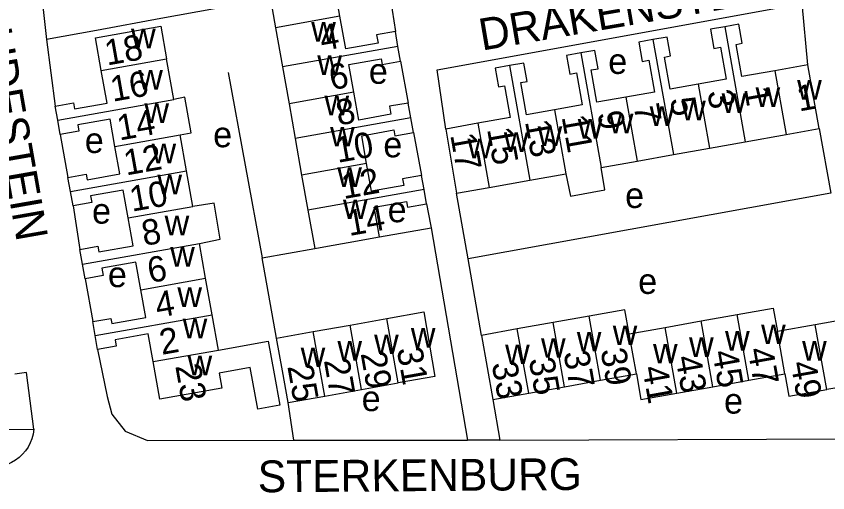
# Model space of a CAD drawing. Extents: x 157794 to 159375, y 380877 to 382306.
# Drawn here: x 158315.9 to 158443.4, y 381261.1 to 381335.9 of the extents above; entities that cross this region are included whole.
import ezdxf

# ---------------------------------------------------------------- set-up
doc = ezdxf.new("R2010")
doc.units = 0
for name, color, linetype in [('BLT_Basislijn', 7, 'Continuous'), ('BLT_Bebouwing', 7, 'Continuous'), ('BLT_Centroide', 7, 'Continuous'), ('BLT_Huisnummer', 7, 'Continuous'), ('BLT_Huisnummer_ tussenligend', 7, 'Continuous'), ('BLT_Onderverdeling_panden', 7, 'Continuous'), ('BLT_Straatnaam', 7, 'Continuous')]:
    doc.layers.add(name, color=color, linetype=linetype)

msp = doc.modelspace()

# ---------------------------------------------------------------- linework, layer by layer
at = {"layer": 'BLT_Basislijn'}
for p, q in [((158319.92, 381339.08), (158320.65, 381332.28)), ((158440.25, 381328.29), (158439.33, 381337.9)), ((158320.65, 381332.28), (158322.04, 381321.82)), ((158376.29, 381328.84), (158377.49, 381322.29)), ((158349.2, 381327.1), (158354.53, 381297.99)), ((158322.84, 381317.36), (158324.05, 381310.61)), ((158378.31, 381317.66), (158379.57, 381310.93)), ((158442.03, 381318.28), (158443.84, 381308.11)), ((158386.88, 381297.83), (158385.08, 381308.12)), ((158443.84, 381308.11), (158386.88, 381297.83)), ((158324.84, 381306.15), (158325.91, 381299.28)), ((158372.98, 381301.26), (158381.06, 381302.68)), ((158381.06, 381302.68), (158386.79, 381269.35)), ((158354.53, 381297.99), (158362.79, 381299.45)), ((158356.81, 381285.35), (158354.53, 381297.99)), ((158388.98, 381285.79), (158386.88, 381297.83)), ((158326.73, 381294.68), (158327.93, 381287.95)), ((158359.49, 381269.34), (158358.61, 381275.23)), ((158390.77, 381275.71), (158391.85, 381269.33)), ((158233.85, 381270.59), (158318.67, 381271.06)), ((158359.49, 381269.34), (158386.79, 381269.35)), ((158391.85, 381269.33), (158386.79, 381269.35))]:
    msp.add_line(p, q, dxfattribs=at)
for points in [[(158361.06, 381341.48), (158366.16, 381342.37), (158373.93, 381343.62), (158375.46, 381333.52)], [(158361.06, 381341.48), (158356.14, 381340.58), (158347.11, 381339.01), (158347.08, 381337.08), (158338.64, 381335.56), (158328.52, 381333.7), (158320.65, 381332.28)], [(158383.36, 381318.2), (158382.01, 381327.5), (158439.33, 381337.9)], [(158380.36, 381306.45), (158380.97, 381303.2), (158381.06, 381302.68)], [(158328.71, 381283.57), (158330.22, 381276.19), (158330.96, 381273.39), (158333.03, 381270.75), (158336.56, 381269.27), (158359.49, 381269.34)], [(158318.67, 381271.06), (158317.52, 381279.98), (158315.72, 381279.71)], [(158391.85, 381269.33), (158447.71, 381269.54), (158449.17, 381270.08), (158449.9, 381270.72), (158450.54, 381272.47), (158449.15, 381278.34)], [(158318.67, 381271.06), (158318.56, 381270.25), (158318.38, 381269.56), (158318.12, 381268.89), (158317.78, 381268.25), (158317.38, 381267.66), (158316.91, 381267.11), (158316.39, 381266.62), (158315.82, 381266.19), (158315.2, 381265.82), (158314.54, 381265.53), (158313.85, 381265.31), (158313.15, 381265.17), (158312.87, 381265.14)]]:
    msp.add_lwpolyline(points, dxfattribs=at)
at = {"layer": 'BLT_Bebouwing'}
for p, q in [((158356.64, 381334.12), (158357.73, 381327.96)), ((158375.87, 381331.18), (158375.46, 381333.52)), ((158376.29, 381328.84), (158375.87, 381331.18)), ((158340.68, 381322.83), (158339.54, 381329.22)), ((158357.73, 381327.96), (158358.76, 381322.17)), ((158440.25, 381328.29), (158435.06, 381327.36)), ((158442.03, 381318.28), (158440.25, 381328.29)), ((158358.76, 381322.17), (158359.72, 381316.74)), ((158377.9, 381319.97), (158377.49, 381322.29)), ((158322.44, 381319.59), (158322.04, 381321.82)), ((158322.84, 381317.36), (158322.44, 381319.59)), ((158378.31, 381317.66), (158377.9, 381319.97)), ((158388.42, 381319.1), (158383.36, 381318.2)), ((158342.67, 381311.62), (158341.66, 381317.28)), ((158383.36, 381318.2), (158385.08, 381308.12)), ((158430.4, 381316.2), (158436.84, 381317.35)), ((158436.84, 381317.35), (158442.03, 381318.28)), ((158359.72, 381316.74), (158360.74, 381310.98)), ((158424.8, 381315.2), (158430.4, 381316.2)), ((158419.12, 381314.19), (158424.8, 381315.2)), ((158413.42, 381313.17), (158419.12, 381314.19)), ((158407.77, 381312.16), (158413.42, 381313.17)), ((158343.66, 381306.05), (158342.67, 381311.62)), ((158360.74, 381310.98), (158361.73, 381305.45)), ((158379.96, 381308.69), (158379.57, 381310.93)), ((158396.58, 381310.17), (158402.22, 381311.17)), ((158324.45, 381308.38), (158324.05, 381310.61)), ((158390.21, 381309.03), (158396.58, 381310.17)), ((158324.84, 381306.15), (158324.45, 381308.38)), ((158380.36, 381306.45), (158379.96, 381308.69)), ((158385.08, 381308.12), (158390.21, 381309.03)), ((158361.73, 381305.45), (158362.79, 381299.45)), ((158326.32, 381296.98), (158325.91, 381299.28)), ((158345.66, 381294.77), (158344.69, 381300.24)), ((158326.73, 381294.68), (158326.32, 381296.98)), ((158346.68, 381289.02), (158345.66, 381294.77)), ((158347.67, 381283.49), (158346.68, 381289.02)), ((158423.49, 381288.06), (158429.14, 381289.07)), ((158328.32, 381285.76), (158327.93, 381287.95)), ((158368.34, 381287.4), (158374.1, 381288.43)), ((158400.24, 381287.8), (158394.61, 381286.8)), ((158405.88, 381288.8), (158400.24, 381287.8)), ((158417.84, 381287.05), (158423.49, 381288.06)), ((158447.34, 381288.52), (158441.39, 381287.46)), ((158362.57, 381286.38), (158368.34, 381287.4)), ((158394.61, 381286.8), (158388.98, 381285.79)), ((158412.18, 381286.04), (158417.84, 381287.05)), ((158441.39, 381287.46), (158435.45, 381286.4)), ((158328.71, 381283.57), (158328.32, 381285.76)), ((158356.81, 381285.35), (158362.57, 381286.38)), ((158388.98, 381285.79), (158390.77, 381275.71)), ((158407.67, 381278.73), (158413.31, 381279.73)), ((158430.98, 381278.73), (158436.64, 381279.74)), ((158370.14, 381277.28), (158375.9, 381278.31)), ((158396.41, 381276.72), (158402.04, 381277.72)), ((158402.04, 381277.72), (158407.67, 381278.73)), ((158419.68, 381276.72), (158425.33, 381277.73)), ((158425.33, 381277.73), (158430.98, 381278.73)), ((158449.15, 381278.34), (158443.21, 381277.28)), ((158358.61, 381275.23), (158364.37, 381276.26)), ((158364.37, 381276.26), (158370.14, 381277.28)), ((158390.77, 381275.71), (158396.41, 381276.72))]:
    msp.add_line(p, q, dxfattribs=at)
for points in [[(158366.76, 381335.91), (158365.85, 381341.03), (158355.73, 381339.23), (158356.64, 381334.12)], [(158375.46, 381333.52), (158372.52, 381332.99), (158372.75, 381331.7), (158367.67, 381330.8), (158366.76, 381335.91)], [(158329.27, 381327.4), (158328.36, 381332.51), (158338.63, 381334.34), (158339.54, 381329.22)], [(158427.18, 381334.27), (158424.96, 381333.87), (158425.49, 381330.86), (158426.51, 381331.04), (158427.41, 381326.02), (158423.01, 381325.24)], [(158435.06, 381327.36), (158429.87, 381326.44), (158428.97, 381331.49), (158429.94, 381331.67), (158429.41, 381334.67), (158427.18, 381334.27)], [(158423.01, 381325.24), (158418.61, 381324.45), (158417.71, 381329.51), (158418.65, 381329.68), (158418.12, 381332.66), (158415.9, 381332.26)], [(158415.9, 381332.26), (158413.68, 381331.86), (158414.22, 381328.82), (158415.25, 381329.01), (158416.14, 381324.01), (158411.63, 381323.2)], [(158404.56, 381330.16), (158402.35, 381329.77), (158402.87, 381326.83), (158403.91, 381327.02), (158404.81, 381321.99), (158400.44, 381321.22)], [(158411.63, 381323.2), (158407.12, 381322.4), (158406.21, 381327.49), (158407.29, 381327.68), (158406.78, 381330.56), (158404.56, 381330.16)], [(158368.93, 381323.98), (158368.15, 381328.34), (158373.23, 381329.24), (158373.39, 381328.33), (158376.29, 381328.84)], [(158400.44, 381321.22), (158396.07, 381320.44), (158395.17, 381325.49), (158396.14, 381325.66), (158395.62, 381328.57), (158393.37, 381328.17)], [(158322.04, 381321.82), (158324.89, 381322.33), (158325.06, 381321.37), (158330.18, 381322.28), (158329.27, 381327.4)], [(158393.37, 381328.17), (158391.12, 381327.77), (158391.64, 381324.83), (158392.59, 381325), (158393.48, 381320), (158388.42, 381319.1)], [(158377.49, 381322.29), (158374.54, 381321.77), (158374.76, 381320.52), (158369.71, 381319.62), (158368.93, 381323.98)], [(158341.66, 381317.28), (158343.39, 381317.6), (158342.4, 381323.19), (158340.68, 381322.83)], [(158331.43, 381315.47), (158330.66, 381319.78), (158325.59, 381318.88), (158325.77, 381317.88), (158322.84, 381317.36)], [(158370.94, 381312.79), (158370.17, 381317.16), (158375.2, 381318.06), (158375.37, 381317.13), (158378.31, 381317.66)], [(158324.05, 381310.61), (158326.92, 381311.12), (158327.08, 381310.24), (158332.19, 381311.15), (158331.43, 381315.47)], [(158379.57, 381310.93), (158376.59, 381310.4), (158376.79, 381309.33), (158371.71, 381308.43), (158370.94, 381312.79)], [(158402.22, 381311.17), (158402.98, 381307.68), (158408.34, 381308.64), (158407.77, 381312.16)], [(158333.49, 381304.24), (158332.71, 381308.61), (158327.58, 381307.7), (158327.77, 381306.67), (158324.84, 381306.15)], [(158344.69, 381300.24), (158347.96, 381300.88), (158346.99, 381306.55), (158343.66, 381306.05)], [(158372.98, 381301.26), (158372.15, 381305.92), (158377.23, 381306.82), (158377.39, 381305.92), (158380.36, 381306.45)], [(158325.91, 381299.28), (158328.76, 381299.79), (158328.91, 381298.91), (158334.27, 381299.86), (158333.49, 381304.24)], [(158362.79, 381299.45), (158364.82, 381299.81), (158368.04, 381300.38), (158372.98, 381301.26)], [(158335.51, 381292.97), (158334.73, 381297.31), (158329.37, 381296.36), (158329.58, 381295.18), (158326.73, 381294.68)], [(158327.93, 381287.95), (158330.8, 381288.46), (158330.94, 381287.67), (158336.28, 381288.62), (158335.51, 381292.97)], [(158374.1, 381288.43), (158379.94, 381289.47), (158381.67, 381279.33), (158375.9, 381278.31)], [(158412.18, 381286.04), (158411.51, 381289.8), (158405.88, 381288.8)], [(158429.14, 381289.07), (158434.8, 381290.07), (158435.45, 381286.4)], [(158337.43, 381281.67), (158336.66, 381286.02), (158331.46, 381285.09), (158331.63, 381284.09), (158328.71, 381283.57)], [(158358.61, 381275.23), (158357.72, 381280.23), (158356.81, 381285.35)], [(158347.67, 381283.49), (158355.51, 381284.89), (158356.42, 381279.75), (158357.3, 381274.83), (158353.85, 381274.2), (158352.68, 381280.75), (158347.79, 381279.88), (158348.21, 381277.5), (158338.48, 381275.77), (158337.43, 381281.67)], [(158413.31, 381279.73), (158414.02, 381275.71), (158419.68, 381276.72)], [(158436.64, 381279.74), (158437.27, 381276.22), (158443.21, 381277.28)]]:
    msp.add_lwpolyline(points, dxfattribs=at)
at = {"layer": 'BLT_Onderverdeling_panden'}
for p, q in [((158366.76, 381335.91), (158356.64, 381334.12)), ((158427.18, 381334.27), (158430.4, 381316.2)), ((158375.87, 381331.18), (158357.73, 381327.96)), ((158415.9, 381332.26), (158419.12, 381314.19)), ((158404.56, 381330.16), (158407.77, 381312.16)), ((158329.27, 381327.4), (158339.54, 381329.22)), ((158393.37, 381328.17), (158396.58, 381310.17)), ((158435.06, 381327.36), (158436.84, 381317.35)), ((158423.01, 381325.24), (158424.8, 381315.2)), ((158368.93, 381323.98), (158358.76, 381322.17)), ((158322.44, 381319.59), (158340.68, 381322.83)), ((158411.63, 381323.2), (158413.42, 381313.17)), ((158400.44, 381321.22), (158402.22, 381311.17)), ((158377.9, 381319.97), (158359.72, 381316.74)), ((158388.42, 381319.1), (158390.21, 381309.03)), ((158331.43, 381315.47), (158341.66, 381317.28)), ((158370.94, 381312.79), (158360.74, 381310.98)), ((158324.45, 381308.38), (158342.67, 381311.62)), ((158379.96, 381308.69), (158361.73, 381305.45)), ((158333.49, 381304.24), (158343.66, 381306.05)), ((158326.32, 381296.98), (158344.69, 381300.24)), ((158335.51, 381292.97), (158345.66, 381294.77)), ((158328.32, 381285.76), (158346.68, 381289.02)), ((158430.98, 381278.73), (158429.14, 381289.07)), ((158375.9, 381278.31), (158374.1, 381288.43)), ((158402.04, 381277.72), (158400.24, 381287.8)), ((158407.67, 381278.73), (158405.88, 381288.8)), ((158425.33, 381277.73), (158423.49, 381288.06)), ((158370.14, 381277.28), (158368.34, 381287.4)), ((158396.41, 381276.72), (158394.61, 381286.8)), ((158419.68, 381276.72), (158417.84, 381287.05)), ((158443.21, 381277.28), (158441.39, 381287.46)), ((158364.37, 381276.26), (158362.57, 381286.38)), ((158413.31, 381279.73), (158412.18, 381286.04)), ((158436.64, 381279.74), (158435.45, 381286.4)), ((158337.43, 381281.67), (158347.67, 381283.49))]:
    msp.add_line(p, q, dxfattribs=at)

# ---------------------------------------------------------------- texts
at = {"layer": 'BLT_Centroide'}
for s, p in [('w', (158362.25, 381331.94)), ('w', (158333.95, 381330.88)), ('e', (158408.89, 381326.86)), ('w', (158363.2, 381326.69)), ('w', (158335.09, 381324.41)), ('e', (158371.3, 381325.31)), ('w', (158432.02, 381321.66)), ('w', (158438.55, 381322.81)), ('w', (158364.33, 381320.38)), ('w', (158426.7, 381320.72)), ('w', (158336.05, 381319.16)), ('w', (158420.34, 381319.58)), ('w', (158415.38, 381318.7)), ('w', (158404.11, 381316.69)), ('w', (158408.98, 381317.55)), ('e', (158346.85, 381315.34)), ('w', (158365.21, 381315.47)), ('w', (158397.8, 381315.56)), ('e', (158326.69, 381314.44)), ('w', (158392.5, 381314.62)), ('w', (158337.17, 381312.84)), ('e', (158373.57, 381313.76)), ('w', (158386.78, 381313.61)), ('w', (158366.34, 381309.12)), ('w', (158338.09, 381307.94)), ('e', (158411.54, 381305.8)), ('w', (158367.23, 381304.06)), ('e', (158327.83, 381303.34)), ('e', (158374.25, 381303.56)), ('w', (158339.23, 381301.5)), ('w', (158340.1, 381296.59)), ('e', (158330.32, 381293.37)), ('e', (158413.59, 381292.3)), ('w', (158341.23, 381290.25)), ('w', (158342.06, 381285.34)), ('w', (158377.89, 381283.88)), ('w', (158409.59, 381284.27)), ('w', (158427.23, 381283.39)), ('w', (158432.89, 381284.41)), ('w', (158372.12, 381282.84)), ('w', (158398.33, 381282.27)), ('w', (158403.95, 381283.27)), ('w', (158421.58, 381282.39)), ('w', (158366.36, 381281.84)), ('w', (158392.69, 381281.27)), ('w', (158415.92, 381281.39)), ('w', (158439.33, 381281.84)), ('w', (158360.59, 381280.81)), ('w', (158342.83, 381279.53)), ('e', (158370.17, 381273.89)), ('e', (158427.07, 381273.5))]:
    msp.add_text(s, height=4, dxfattribs=at).set_placement(p)
at = {"layer": 'BLT_Huisnummer'}
for s, rotation, p in [('18', 10.0675, (158330.18, 381328.17)), ('6', 10.0754, (158365.43, 381324.3)), ('1', 10.1154, (158438.86, 381320.95)), ('1', 280.0962, (158430.2, 381324.53)), ('5', 280.0962, (158418.55, 381322.91)), ('14', 10.084, (158332.13, 381316.39)), ('9', 280.0962, (158407.17, 381320.75)), ('13', 280.0962, (158395.81, 381319.37)), ('10', 10.0754, (158366.4, 381312.88)), ('17', 280.0962, (158384.07, 381317.27)), ('10', 10.084, (158334.1, 381305.21)), ('14', 10.0754, (158368.21, 381301.39)), ('6', 10.084, (158336.9, 381294)), ('2', 10.084, (158338.78, 381282.72)), ('31', 280.078, (158375.66, 381283.65)), ('37', 280.1036, (158401.84, 381283.08)), ('45', 280.1036, (158425.2, 381283.17)), ('33', 280.1036, (158390.57, 381281.36)), ('23', 280.0832, (158340.89, 381280.99)), ('25', 280.0818, (158358.49, 381280.93)), ('41', 280.1036, (158414.21, 381280.71))]:
    msp.add_text(s, height=4, rotation=rotation, dxfattribs=at).set_placement(p)
at = {"layer": 'BLT_Huisnummer_ tussenligend'}
for s, rotation, p in [('4', 10.0754, (158363.95, 381330.46)), ('16', 10.084, (158331.07, 381322.48)), ('3', 280.0962, (158424.43, 381324.05)), ('8', 10.0754, (158366.5, 381318.74)), ('7', 280.0962, (158412.85, 381321.86)), ('11', 280.0962, (158401.56, 381320.12)), ('15', 280.0962, (158389.85, 381318.18)), ('12', 10.084, (158333.18, 381310.9)), ('12', 10.0754, (158367.34, 381307.19)), ('8', 10.084, (158335.99, 381299.83)), ('4', 10.084, (158338.11, 381288.54)), ('29', 280.0818, (158369.99, 381282.96)), ('39', 280.1036, (158407.66, 381283.47)), ('47', 280.1036, (158430.76, 381283.58)), ('27', 280.0818, (158364.22, 381281.87)), ('35', 280.1036, (158396.39, 381282.02)), ('43', 280.1036, (158419.42, 381282.34)), ('49', 280.1036, (158437.51, 381281.45))]:
    msp.add_text(s, height=4, rotation=rotation, dxfattribs=at).set_placement(p)
at = {"layer": 'BLT_Straatnaam'}
for s, rotation, p in [('GOUDESTEIN', 279.959, (158308.39, 381343.89)), ('DRAKENSTEIN', 9.7183, (158389.05, 381330.51)), ('STERKENBURG', 0.4355, (158353.87, 381261.13))]:
    msp.add_text(s, height=5, rotation=rotation, dxfattribs=at).set_placement(p)

doc.saveas('drawing.dxf')
